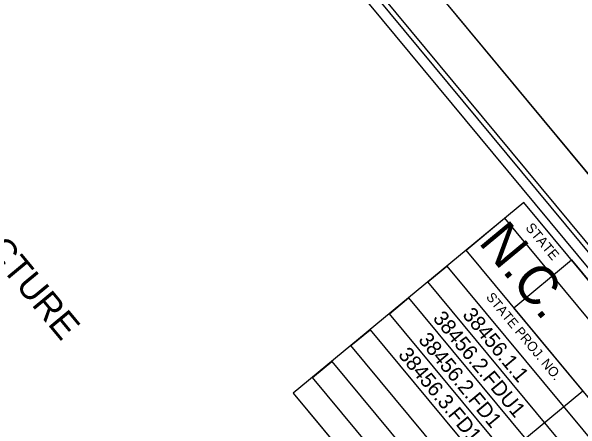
# Model space of a CAD drawing. Extents: x 2054826 to 2060231, y 685508 to 690809.
# Drawn here: x 2059518.7 to 2059946.5, y 688509.7 to 688824.4 of the extents above; entities that cross this region are included whole.
import ezdxf

# ---------------------------------------------------------------- set-up
doc = ezdxf.new("R2010")
doc.units = 0
for name, color, linetype in [('Sheet Cutting Line CELL', 7, 'Continuous'), ('Sheet Data Field CELL', 7, 'Continuous'), ('Sheet Plot Border Inside CELL', 7, 'Continuous'), ('Sheet Plot Border Outside CELL', 7, 'Continuous'), ('Sheet Title CELL', 7, 'Continuous')]:
    doc.layers.add(name, color=color, linetype=linetype)

msp = doc.modelspace()

# ---------------------------------------------------------------- linework, layer by layer
at = {"layer": 'Sheet Cutting Line CELL'}
msp.add_line((2058618.84, 690310.09), (2060231.25, 688365.67), dxfattribs=at)
at = {"layer": 'Sheet Plot Border Inside CELL'}
msp.add_lwpolyline([(2057387.09, 689263.34), (2058982.75, 687339.12), (2060201.02, 688349.37), (2058605.36, 690273.59)], close=True, dxfattribs=at)
at = {"layer": 'Sheet Plot Border Outside CELL'}
msp.add_lwpolyline([(2060231.25, 688365.67), (2058618.84, 690310.09), (2057348.74, 689256.87), (2058961.15, 687312.44)], close=True, dxfattribs=at)
at = {"layer": 'Sheet Title CELL'}
for points in [[(2060176.54, 688372.89), (2058759.45, 690081.81)], [(2060165.97, 688373.89), (2058806.35, 690013.48)], [(2060167.11, 688363.15), (2059903.79, 688680.66), (2059730.61, 688537.05), (2059818.34, 688431.22), (2059948.24, 688538.93), (2059896.39, 688601.46), (2059939.71, 688637.38), (2060095.3, 688449.72)], [(2060123.81, 688327.24), (2059860.5, 688644.77), (2059889.37, 688668.71), (2060152.68, 688351.18)], [(2060094.93, 688303.29), (2059831.62, 688620.82), (2059846.06, 688632.79), (2060109.37, 688315.26)], [(2060066.08, 688279.37), (2059802.77, 688596.89), (2059817.19, 688608.85), (2060080.51, 688291.33)], [(2060037.2, 688255.42), (2059773.9, 688572.93), (2059788.34, 688584.93), (2060051.65, 688267.4)], [(2060008.33, 688231.48), (2059745.04, 688549.02), (2059759.46, 688560.98), (2060022.77, 688243.45)], [(2059730.61, 688537.05), (2059993.92, 688219.52)]]:
    msp.add_lwpolyline(points, dxfattribs=at)

# ---------------------------------------------------------------- texts
at = {"layer": 'Sheet Data Field CELL'}
for s, height, p in [('GRADING, PAVING, DRAINAGE, AND STRUCTURE ', 19.5314, (2059158.3, 689056)), ('38456.2.FDU1', 11.25, (2059834.95, 688593.19)), ('38456.1.1 ', 11.25, (2059857.15, 688595.8)), ('38456.2.FD1', 11.25, (2059824.03, 688577.01)), ('38456.3.FD1', 11.25, (2059808.92, 688565.86))]:
    msp.add_text(s, height=height, rotation=309.6672, dxfattribs=at).set_placement(p)
at = {"layer": 'Sheet Title CELL'}
for s, height, p in [('N.C.', 29.025, (2059869.13, 688650.46)), ('STATE', 7.5, (2059904.67, 688661.42)), ('STATE PROJ. NO.', 7.2, (2059875.08, 688609.21))]:
    msp.add_text(s, height=height, rotation=309.6672, dxfattribs=at).set_placement(p)

doc.saveas('drawing.dxf')
